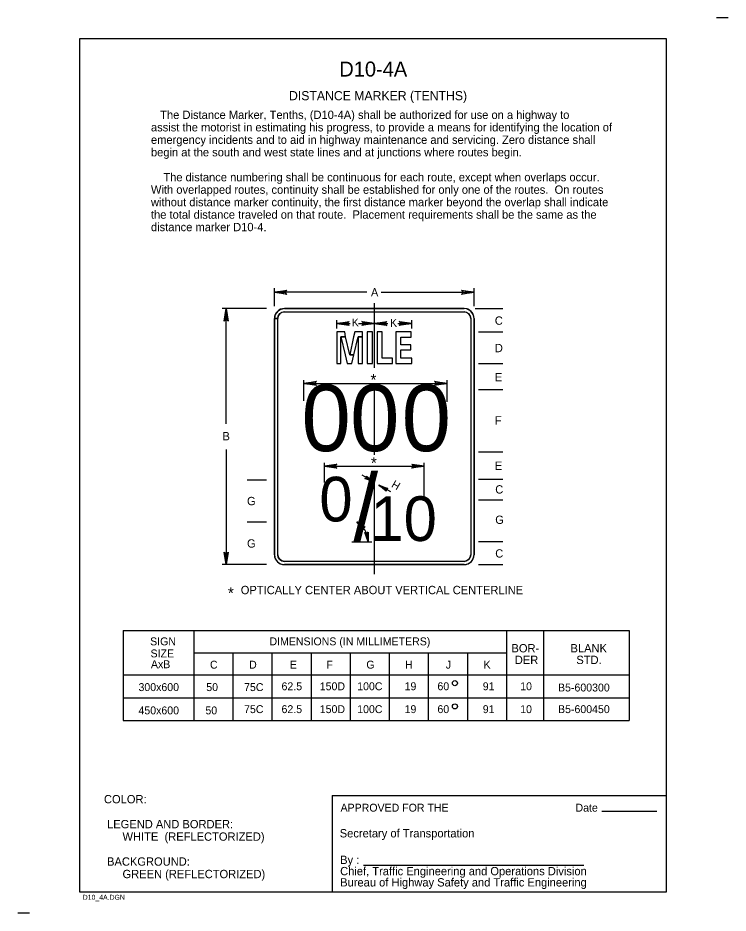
# Model space of a CAD drawing. Extents: x -0.018 to 0.195, y -0.006 to 0.263.
import ezdxf

# ---------------------------------------------------------------- set-up
doc = ezdxf.new("R2010")
doc.units = 0
for name, color, linetype in [('1', 7, 'Continuous'), ('2', 7, 'Continuous'), ('3', 7, 'Continuous')]:
    doc.layers.add(name, color=color, linetype=linetype)

# ---------------------------------------------------------------- blocks, each defined once
blk = doc.blocks.new('RARROW')
at = {"layer": '3'}
for p, q in [((-2.156, 0.285), (-2.2665, 0.384625)), ((-2.2665, 0.384625), (0, 0)), ((0, 0), (-2.2665, -0.379125)), ((-2.156, 0.285), (-2.075625, 0.12075)), ((0, 0), (-2.156, 0.285)), ((-2.14975, -0.2705), (0, 0)), ((-2.075625, 0.12075), (0, 0)), ((0, 0), (-2.074, -0.108)), ((-2.2665, -0.379125), (-2.14975, -0.2705)), ((-2.074, -0.108), (-2.14975, -0.2705))]:
    blk.add_line(p, q, dxfattribs=at)

msp = doc.modelspace()

# ---------------------------------------------------------------- linework, layer by layer
at = {"layer": '1'}
for p, q in [((0.195, 0.26275), (0.1915, 0.26275)), ((0.1765, 0.2565), (0, 0.2565)), ((0, 0.2565), (0, 0)), ((0.1765, 0), (0.1765, 0.2565)), ((0.088625, 0.177), (0.088625, 0.1575)), ((0.077375, 0.169375), (0.077375, 0.171875)), ((0.077375, 0.170875), (0.081375, 0.170875)), ((0.083875, 0.170875), (0.088625, 0.170875)), ((0.088625, 0.170875), (0.09275, 0.170875)), ((0.09575, 0.170875), (0.099875, 0.170875)), ((0.099875, 0.169375), (0.099875, 0.171875)), ((0.0675, 0.147625), (0.0675, 0.153875)), ((0.1105, 0.147375), (0.1105, 0.153875)), ((0.0675, 0.152875), (0.1105, 0.152875)), ((0.088625, 0.15175), (0.088625, 0.131375)), ((0.073625, 0.123125), (0.073625, 0.129)), ((0.073625, 0.128), (0.103625, 0.128)), ((0.103625, 0.117625), (0.103625, 0.129)), ((0.0885, 0.12325), (0.085, 0.12525)), ((0.088625, 0.12575), (0.088625, 0.0955)), ((0.093625, 0.12025), (0.09, 0.12225)), ((0.081875, 0.10525), (0.087875, 0.10525)), ((0.076, 0.029), (0.1765, 0.029)), ((0.076, 0.029), (0.076, 0)), ((0.157, 0.02425), (0.173625, 0.02425)), ((0.085375, 0.008), (0.151625, 0.008)), ((0, 0), (0.1765, 0)), ((-0.015, -0.006375), (-0.0185, -0.006375))]:
    msp.add_line(p, q, dxfattribs=at)
for points in [[(0.077375, 0.1615), (0.077375, 0.158875), (0.078625, 0.158875), (0.078625, 0.1615), (0.078625, 0.166875), (0.08, 0.166875), (0.07975, 0.168375), (0.077375, 0.168375), (0.077375, 0.166875)], [(0.079875, 0.1615), (0.0805, 0.158875), (0.081875, 0.158875), (0.0825, 0.1615), (0.08125, 0.1615), (0.08, 0.166875), (0.078625, 0.166875)], [(0.082375, 0.166875), (0.08125, 0.1615), (0.0825, 0.1615), (0.08375, 0.166875), (0.085125, 0.166875), (0.085125, 0.168375), (0.08275, 0.168375)], [(0.08375, 0.1615), (0.08375, 0.158875), (0.085125, 0.158875), (0.085125, 0.1615), (0.085125, 0.166875), (0.08375, 0.166875)], [(0.0865, 0.168375), (0.0865, 0.158875), (0.088125, 0.158875), (0.088125, 0.168375)], [(0.0895, 0.1605), (0.0895, 0.158875), (0.094125, 0.158875), (0.094125, 0.1605), (0.091, 0.1605), (0.091, 0.168375), (0.0895, 0.168375)], [(0.095125, 0.1605), (0.095125, 0.158875), (0.099875, 0.158875), (0.099875, 0.1605), (0.096625, 0.1605), (0.096625, 0.163), (0.099625, 0.163), (0.099625, 0.1645), (0.096625, 0.1645), (0.096625, 0.16675), (0.09975, 0.16675), (0.09975, 0.168375), (0.095125, 0.168375), (0.095125, 0.16675), (0.095125, 0.1645), (0.095125, 0.163)]]:
    msp.add_lwpolyline(points, close=True, dxfattribs=at)
for points in [[(0.08625, 0.124875), (0.08625, 0.124625), (0.0885, 0.12325), (0.08625, 0.124875), (0.08625, 0.125), (0.0885, 0.12325), (0.086125, 0.1245), (0.086, 0.12425), (0.0885, 0.12325), (0.08575, 0.12425), (0.086, 0.12425)], [(0.09225, 0.12075), (0.09225, 0.120875), (0.09, 0.12225), (0.09225, 0.12075), (0.09225, 0.1205), (0.09, 0.12225), (0.092375, 0.121), (0.0925, 0.12125), (0.09, 0.12225), (0.09275, 0.12125), (0.0925, 0.12125)], [(0.08525, 0.109), (0.085375, 0.109375), (0.083375, 0.11125), (0.08525, 0.109), (0.08525, 0.108875), (0.083375, 0.11125), (0.0855, 0.1095), (0.08575, 0.109625), (0.083375, 0.11125), (0.085875, 0.109625), (0.08575, 0.109625)], [(0.086625, 0.108), (0.0865, 0.108), (0.08675, 0.10525), (0.086625, 0.108), (0.08675, 0.108125), (0.08675, 0.10525), (0.086125, 0.10775), (0.086, 0.108), (0.08675, 0.10525), (0.08575, 0.108), (0.086, 0.108)]]:
    msp.add_lwpolyline(points, dxfattribs=at)
msp.add_arc((0.080094, 0.105264), 0.006718, 15.45208, 60.03334, dxfattribs=at)
at = {"layer": '3'}
for p, q in [((0.058625, 0.176125), (0.058625, 0.1815)), ((0.118625, 0.176125), (0.118625, 0.1815)), ((0.086375, 0.18025), (0.058625, 0.18025)), ((0.09075, 0.18025), (0.118625, 0.18025)), ((0.05625, 0.175375), (0.042875, 0.175375)), ((0.044125, 0.14075), (0.044125, 0.175375)), ((0.061625, 0.175375), (0.115625, 0.175375)), ((0.119, 0.175375), (0.12725, 0.175375)), ((0.058625, 0.101375), (0.058625, 0.172375)), ((0.059625, 0.101375), (0.059625, 0.172375)), ((0.061625, 0.174375), (0.115625, 0.174375)), ((0.117625, 0.172375), (0.117625, 0.101375)), ((0.118625, 0.172375), (0.118625, 0.101375)), ((0.12, 0.168375), (0.12725, 0.168375)), ((0.12, 0.158875), (0.12725, 0.158875)), ((0.12, 0.151), (0.12725, 0.151)), ((0.044125, 0.133), (0.044125, 0.098375)), ((0.12, 0.13225), (0.12725, 0.13225)), ((0.12, 0.124125), (0.12725, 0.124125)), ((0.05625, 0.12375), (0.050375, 0.12375)), ((0.12, 0.117875), (0.12725, 0.117875)), ((0.05625, 0.111125), (0.050375, 0.111125)), ((0.12, 0.105375), (0.12725, 0.105375)), ((0.05625, 0.098375), (0.042875, 0.098375)), ((0.115625, 0.099375), (0.061625, 0.099375)), ((0.115625, 0.098375), (0.061625, 0.098375)), ((0.12, 0.098375), (0.12725, 0.098375)), ((0.013125, 0.078625), (0.013125, 0.0515)), ((0.013125, 0.078625), (0.16525, 0.078625)), ((0.034375, 0.078625), (0.034375, 0.0515)), ((0.128375, 0.078625), (0.128375, 0.0515)), ((0.1395, 0.078625), (0.1395, 0.0515)), ((0.16525, 0.078625), (0.16525, 0.0515)), ((0.128375, 0.07175), (0.034375, 0.07175)), ((0.046125, 0.07175), (0.046125, 0.0515)), ((0.057875, 0.07175), (0.057875, 0.0515)), ((0.069625, 0.07175), (0.069625, 0.0515)), ((0.081375, 0.07175), (0.081375, 0.0515)), ((0.093125, 0.07175), (0.093125, 0.0515)), ((0.104875, 0.07175), (0.104875, 0.0515)), ((0.116625, 0.07175), (0.116625, 0.0515)), ((0.013125, 0.06525), (0.16525, 0.06525)), ((0.013125, 0.058375), (0.16525, 0.058375)), ((0.013125, 0.0515), (0.16525, 0.0515))]:
    msp.add_line(p, q, dxfattribs=at)
msp.add_lwpolyline([(0.058625, 0.172375), (0.058625, 0.101375), (0.058875, 0.100125), (0.0595, 0.09925), (0.060375, 0.098625), (0.061625, 0.098375), (0.115625, 0.098375), (0.116875, 0.098625), (0.117875, 0.099375), (0.118375, 0.10025), (0.118625, 0.101375), (0.118625, 0.172375), (0.118375, 0.173625), (0.117625, 0.174625), (0.1165, 0.17525), (0.115625, 0.175375), (0.061625, 0.175375), (0.0605, 0.175125), (0.059625, 0.174625), (0.058875, 0.173625), (0.058625, 0.172375), (0.059625, 0.172375), (0.05975, 0.173125), (0.06025, 0.173875), (0.060875, 0.17425), (0.061625, 0.174375), (0.115625, 0.174375), (0.116375, 0.17425), (0.117, 0.173875), (0.1175, 0.173125), (0.117625, 0.172375), (0.117625, 0.101375), (0.1175, 0.100625), (0.117125, 0.1), (0.116375, 0.0995), (0.115625, 0.099375), (0.061625, 0.099375), (0.060875, 0.0995), (0.060125, 0.1), (0.05975, 0.100625), (0.059625, 0.101375), (0.059625, 0.172375)], close=True, dxfattribs=at)
for centre in [(0.112875, 0.06275), (0.112875, 0.05575)]:
    msp.add_circle(centre, 0.00076, dxfattribs=at)
for centre, radius, start, end in [((0.061625, 0.172375), 0.003, 90, 180), ((0.115625, 0.172375), 0.003, 0, 90), ((0.061625, 0.172375), 0.002, 90, 180), ((0.115625, 0.172375), 0.002, 0, 90), ((0.061625, 0.101375), 0.003, 180, 270), ((0.061625, 0.101375), 0.002, 180, 270), ((0.115625, 0.101375), 0.003, 270, 0), ((0.115625, 0.101375), 0.002, 270, 0)]:
    msp.add_arc(centre, radius, start, end, dxfattribs=at)

# ---------------------------------------------------------------- block references
at = {"layer": '3', "xscale": 0.0016545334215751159, "yscale": 0.0016366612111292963}
for p, rotation in [((0.058625, 0.18025), 180), ((0.044125, 0.175375), 90), ((0.077375, 0.170875), 180), ((0.088625, 0.170875), 180), ((0.0675, 0.152875), 180), ((0.073625, 0.128), 180), ((0.044125, 0.098375), -90)]:
    msp.add_blockref('RARROW', p, dxfattribs=dict(at, rotation=rotation))
for p in [(0.118625, 0.18025), (0.088625, 0.170875), (0.099875, 0.170875), (0.1105, 0.152875), (0.103625, 0.128)]:
    msp.add_blockref('RARROW', p, dxfattribs=at)

# ---------------------------------------------------------------- texts
at = {"layer": '1'}
for s, height, p in [('D10-4A', 0.0045, (0.078125, 0.245125)), ('DISTANCE MARKER (TENTHS)', 0.00275025, (0.063, 0.238)), ('K', 0.002375, (0.081875, 0.17)), ('K', 0.002375, (0.093375, 0.169875)), ('*', 0.00342, (0.0875, 0.15225)), ('0', 0.019928, (0.06675, 0.1325)), ('0', 0.019928, (0.081375, 0.1325)), ('0', 0.019928, (0.096875, 0.1325)), ('*', 0.00342, (0.087625, 0.12725)), ('/', 0.019928, (0.082375, 0.105625)), ('0', 0.013413, (0.072125, 0.111375)), ('10', 0.013413, (0.0875, 0.1055)), ('J', 0.002375, (0.082875, 0.10625)), ('*', 0.00342, (0.044625, 0.088125)), ('COLOR:', 0.0024998, (0.007375, 0.026625)), ('APPROVED FOR THE', 0.00237525, (0.0785, 0.024125)), ('Date ', 0.0023752, (0.149125, 0.024125)), (' LEGEND AND BORDER:', 0.00249975, (0.007375, 0.019125)), ('Secretary of Transportation', 0.00249975, (0.07825, 0.016375)), ('      WHITE  (REFLECTORIZED)', 0.00249975, (0.007375, 0.015375)), ('By :', 0.0024998, (0.078375, 0.008375)), (' BACKGROUND:', 0.00249975, (0.007375, 0.007875)), ('      GREEN (REFLECTORIZED)', 0.00249975, (0.007375, 0.004125)), ('Chief, Traffic Engineering and Operations Division', 0.00249975, (0.078375, 0.005)), ('Bureau of Highway Safety and Traffic Engineering', 0.00249975, (0.078375, 0.001625)), ('D10_4A.DGN', 0.0015, (0.001, -0.002375))]:
    msp.add_text(s, height=height, dxfattribs=at).set_placement(p)
msp.add_text('H', height=0.002375, rotation=150, dxfattribs=at).set_placement((0.09675, 0.12275))
at = {"layer": '2'}
for s, p in [('   The Distance Marker, Tenths, (D10-4A) shall be authorized for use on a highway to', (0.0215, 0.232375)), ('assist the motorist in estimating his progress, to provide a means for identifying the location of', (0.0215, 0.228625)), ('emergency incidents and to aid in highway maintenance and servicing. Zero distance shall', (0.0215, 0.224875)), ('begin at the south and west state lines and at junctions where routes begin.', (0.0215, 0.221125)), ('    The distance numbering shall be continuous for each route, except when overlaps occur.', (0.0215, 0.213625)), ('With overlapped routes, continuity shall be established for only one of the routes.  On routes', (0.0215, 0.209875)), ('without distance marker continuity, the first distance marker beyond the overlap shall indicate', (0.0215, 0.206125)), ('the total distance traveled on that route.  Placement requirements shall be the same as the', (0.0215, 0.202375)), ('distance marker D10-4.', (0.0215, 0.198625))]:
    msp.add_text(s, height=0.00249975, dxfattribs=at).set_placement(p)
at = {"layer": '3'}
for s, height, p in [('A', 0.0025, (0.087625, 0.179)), ('C', 0.0025, (0.124875, 0.1705)), ('D', 0.0025, (0.124875, 0.16225)), ('E', 0.0025, (0.124875, 0.1535)), ('F', 0.0025, (0.124875, 0.1405)), ('B', 0.0025, (0.043, 0.13575)), ('E', 0.0025, (0.124875, 0.126875)), ('C', 0.0025, (0.125, 0.11975)), ('G', 0.0025, (0.050375, 0.11625)), ('G', 0.0025, (0.125, 0.110625)), ('G', 0.0025, (0.050375, 0.1035)), ('C', 0.0025, (0.125, 0.1005)), ('OPTICALLY CENTER ABOUT VERTICAL CENTERLINE', 0.00249975, (0.0485, 0.0895)), ('SIGN', 0.0023752, (0.02125, 0.074125)), ('DIMENSIONS (IN MILLIMETERS)', 0.00237525, (0.057125, 0.074125)), ('SIZE', 0.0023752, (0.021375, 0.0705)), ('BOR-', 0.0024998, (0.129875, 0.072)), ('BLANK', 0.0024998, (0.147625, 0.072)), ('DER', 0.0024998, (0.130875, 0.0685)), ('STD.', 0.0024998, (0.149375, 0.0685)), ('AxB', 0.0023752, (0.0215, 0.06725)), ('C', 0.002375, (0.03925, 0.067125)), ('D', 0.002375, (0.051, 0.067125)), ('E', 0.002375, (0.06325, 0.067125)), ('F', 0.002375, (0.07425, 0.067125)), ('G', 0.002375, (0.08625, 0.067125)), ('H', 0.002375, (0.097875, 0.067125)), ('J', 0.002375, (0.110125, 0.067125)), ('K', 0.002375, (0.1215, 0.067125)), ('300x600', 0.0023752, (0.01775, 0.060375)), ('50', 0.0023752, (0.038125, 0.060375)), ('75C', 0.0023752, (0.0495, 0.060375)), ('62.5', 0.0023752, (0.06075, 0.060625)), ('150D', 0.0023752, (0.07225, 0.060625)), ('100C', 0.0023752, (0.0835, 0.060625)), ('19', 0.0023752, (0.09775, 0.060625)), ('60', 0.0023752, (0.107625, 0.060625)), ('91', 0.0023752, (0.12125, 0.060625)), ('10', 0.0023752, (0.1325, 0.060625)), ('B5-600300', 0.0023752, (0.143875, 0.06025)), ('450x600', 0.0023752, (0.01775, 0.053375)), ('50', 0.0023752, (0.037875, 0.053375)), ('75C', 0.0023752, (0.0495, 0.05375)), ('62.5', 0.0023752, (0.06075, 0.05375)), ('150D', 0.0023752, (0.07225, 0.05375)), ('100C', 0.0023752, (0.0835, 0.05375)), ('19', 0.0023752, (0.09775, 0.05375)), ('60', 0.0023752, (0.107625, 0.05375)), ('91', 0.0023752, (0.12125, 0.05375)), ('10', 0.0023752, (0.1325, 0.05375)), ('B5-600450', 0.0023752, (0.143875, 0.05375))]:
    msp.add_text(s, height=height, dxfattribs=at).set_placement(p)

doc.saveas('drawing.dxf')
